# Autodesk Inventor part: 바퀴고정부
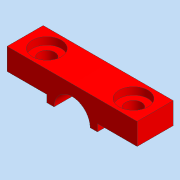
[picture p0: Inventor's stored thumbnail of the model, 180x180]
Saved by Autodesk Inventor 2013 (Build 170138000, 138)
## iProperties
Company: 한국ATC센터
Created: 2015-05
Part Number: 바퀴고정부
Document SubType Name: 모델링
Designer: KYOUNG IL JANG
Vendor: CBT Solutions
Material: 일반
Author: KYOUNG IL JANG
Comments: 파생
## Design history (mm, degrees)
derived "바퀴고정부.ipt"
node "솔리드1"
node "솔리드 본체"
node "곡면 본체"
feature "솔리드1::바퀴고정부.ipt" dims "d0" = 10
tag "피쳐 태그1"
